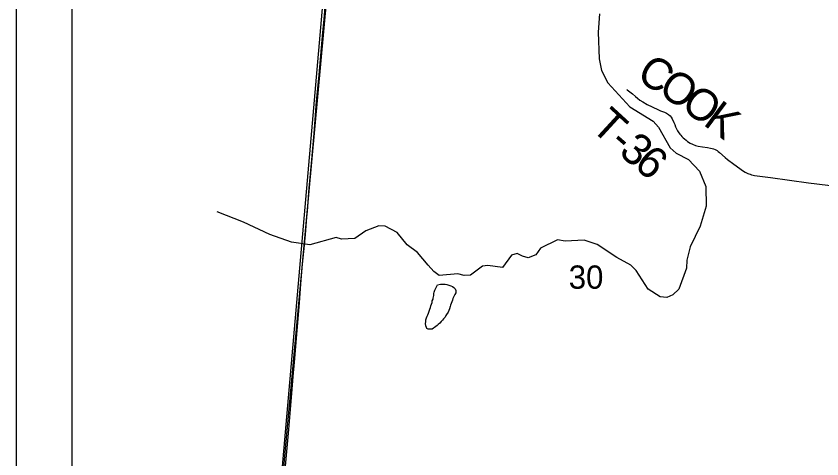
# Model space of a CAD drawing. Extents: x -19.5 to 44.1, y 0 to 22.
# Drawn here: x -19.313 to -17.865, y 16.054 to 16.851 of the extents above; entities that cross this region are included whole.
import ezdxf

# ---------------------------------------------------------------- set-up
doc = ezdxf.new("R2010")
doc.units = 0
for name, color, linetype in [('GM_X_County_Road', 7, 'Continuous'), ('GM_X_Minor_Lake', 7, 'Continuous'), ('GM_X_Minor_River', 7, 'Continuous'), ('GM_X_Section', 7, 'Continuous'), ('GM_X_Section_Text', 7, 'Continuous'), ('GM_X_Township', 7, 'Continuous'), ('GM_X_Township_Road', 7, 'Continuous'), ('GM_X_Township_Road_Text', 7, 'Continuous'), ('SH_Data', 7, 'Continuous')]:
    doc.layers.add(name, color=color, linetype=linetype)

msp = doc.modelspace()

# ---------------------------------------------------------------- linework, layer by layer
at = {"layer": 'GM_X_County_Road'}
msp.add_lwpolyline([(-18.8304, 16.0218), (-18.827, 16.0609), (-18.8229, 16.1073), (-18.8176, 16.1717), (-18.8151, 16.2027), (-18.8129, 16.228), (-18.8038, 16.3352), (-18.8012, 16.3686), (-18.7982, 16.4045), (-18.795, 16.4386), (-18.7932, 16.4577), (-18.792, 16.4732), (-18.7903, 16.4892), (-18.7893, 16.4998), (-18.7861, 16.5412), (-18.7824, 16.5858), (-18.7776, 16.6397), (-18.7729, 16.6973), (-18.7685, 16.7448), (-18.7615, 16.8213), (-18.7596, 16.8446), (-18.7578, 16.8675)], dxfattribs=at)
at = {"layer": 'GM_X_Minor_Lake'}
msp.add_lwpolyline([(-18.5556, 16.3673), (-18.5502, 16.3684), (-18.546, 16.3687), (-18.5419, 16.3686), (-18.5388, 16.3682), (-18.5354, 16.367), (-18.5316, 16.3655), (-18.529, 16.3643), (-18.5263, 16.3624), (-18.5241, 16.36), (-18.5226, 16.3574), (-18.523, 16.3532), (-18.5246, 16.3502), (-18.5258, 16.3475), (-18.5269, 16.3453), (-18.5281, 16.3426), (-18.5289, 16.34), (-18.5301, 16.3366), (-18.5312, 16.3335), (-18.5324, 16.3309), (-18.5332, 16.3286), (-18.5344, 16.3244), (-18.5364, 16.3184), (-18.5394, 16.3142), (-18.541, 16.312), (-18.5422, 16.3093), (-18.5449, 16.3063), (-18.5468, 16.3037), (-18.5491, 16.3011), (-18.5518, 16.2981), (-18.5545, 16.2962), (-18.5564, 16.2943), (-18.5587, 16.2921), (-18.5652, 16.2876), (-18.5694, 16.2876), (-18.5724, 16.2877), (-18.5747, 16.2885), (-18.5754, 16.2904), (-18.5769, 16.2938), (-18.5773, 16.2976), (-18.5768, 16.301), (-18.5764, 16.3041), (-18.5752, 16.3079), (-18.5741, 16.3109), (-18.5729, 16.3135), (-18.5721, 16.3166), (-18.5705, 16.32), (-18.5694, 16.3234), (-18.5682, 16.3268), (-18.5678, 16.3294), (-18.5666, 16.3325), (-18.5654, 16.3355), (-18.565, 16.3385), (-18.5635, 16.3415), (-18.5634, 16.3434), (-18.563, 16.3457), (-18.5622, 16.3484), (-18.5622, 16.3518), (-18.5614, 16.3541), (-18.5602, 16.3575), (-18.5556, 16.3673)], dxfattribs=at)
at = {"layer": 'GM_X_Minor_River'}
msp.add_lwpolyline([(-18.2646, 16.8548), (-18.2668, 16.8218), (-18.265, 16.7739), (-18.2609, 16.7529), (-18.2496, 16.731), (-18.2102, 16.6876), (-18.1682, 16.662), (-18.1585, 16.6508), (-18.1376, 16.6139), (-18.1268, 16.6041), (-18.1046, 16.5927), (-18.0846, 16.5717), (-18.0733, 16.5445), (-18.0729, 16.5088), (-18.0838, 16.4729), (-18.1016, 16.4357), (-18.1074, 16.4119), (-18.1081, 16.3974), (-18.1221, 16.3594), (-18.1325, 16.3493), (-18.1433, 16.3446), (-18.1558, 16.3456), (-18.1771, 16.3594), (-18.1985, 16.3929), (-18.2085, 16.4026), (-18.2333, 16.4165), (-18.2689, 16.4396), (-18.2919, 16.4477), (-18.3265, 16.4458), (-18.3401, 16.4484), (-18.3704, 16.4335), (-18.3789, 16.4215), (-18.3927, 16.4157), (-18.4029, 16.419), (-18.4127, 16.4234), (-18.4226, 16.4205), (-18.439, 16.3988), (-18.4651, 16.4024), (-18.475, 16.4008), (-18.4961, 16.3849), (-18.5076, 16.384), (-18.5193, 16.3873), (-18.5527, 16.3842), (-18.5624, 16.3912), (-18.5725, 16.4025), (-18.5917, 16.4253), (-18.6101, 16.4394), (-18.6279, 16.4614), (-18.65, 16.4729), (-18.6614, 16.4732), (-18.6847, 16.4642), (-18.704, 16.4505), (-18.7283, 16.4495), (-18.7381, 16.4524), (-18.785, 16.4394), (-18.8179, 16.4442), (-18.8568, 16.458), (-18.9041, 16.4803), (-18.9516, 16.4984)], dxfattribs=at)
at = {"layer": 'GM_X_Section'}
msp.add_line((-19.213, 16.9896), (-19.213, 15.9662), dxfattribs=at)
for points in [[(-19.213, 15.9662), (-18.8417, 15.9351), (-18.7487, 16.948), (-19.213, 16.9896)], [(-18.8417, 15.9351), (-18.7487, 16.948)]]:
    msp.add_lwpolyline(points, dxfattribs=at)
at = {"layer": 'GM_X_Township'}
msp.add_lwpolyline([(-17.3561, 18.1443), (-17.4643, 17.7858), (-17.649, 17.1741), (-17.7449, 16.8564), (-17.7682, 16.8751), (-17.7757, 16.8847), (-17.8063, 16.9097), (-17.826, 16.9172), (-17.8465, 16.92), (-17.8664, 16.9161), (-17.9065, 16.8978), (-17.926, 16.8931), (-18.0112, 16.8966), (-18.0543, 16.8933), (-18.1184, 16.8749), (-18.1478, 16.8725), (-18.1785, 16.8797), (-18.2096, 16.8937), (-18.2423, 16.9001), (-18.7562, 16.9411), (-18.7834, 16.6305), (-18.8446, 15.9307), (-18.9306, 14.9193), (-19.0014, 14.1)], dxfattribs=at)
at = {"layer": 'GM_X_Township_Road'}
msp.add_lwpolyline([(-18.2154, 16.7192), (-18.2149, 16.7183), (-18.2055, 16.7107), (-18.2001, 16.7062), (-18.1964, 16.703), (-18.1919, 16.6996), (-18.1867, 16.6964), (-18.1786, 16.692), (-18.17, 16.6875), (-18.1586, 16.6821), (-18.1547, 16.6804), (-18.1478, 16.678), (-18.144, 16.6762), (-18.1404, 16.6739), (-18.1377, 16.6715), (-18.1357, 16.6692), (-18.1339, 16.6661), (-18.131, 16.6594), (-18.1294, 16.6555), (-18.1277, 16.6516), (-18.1255, 16.6467), (-18.1244, 16.6446), (-18.1231, 16.6424), (-18.1203, 16.6385), (-18.1186, 16.6364), (-18.1167, 16.6344), (-18.1142, 16.632), (-18.1118, 16.6299), (-18.109, 16.6275), (-18.1061, 16.6254), (-18.1015, 16.6224), (-18.0972, 16.6201), (-18.0922, 16.6181), (-18.0873, 16.6169), (-18.0794, 16.6155), (-18.0703, 16.6143), (-18.0648, 16.6134), (-18.0621, 16.6128), (-18.0594, 16.612), (-18.0565, 16.6108), (-18.0533, 16.609), (-18.051, 16.6073), (-18.0489, 16.6056), (-18.0386, 16.5966), (-18.0343, 16.593), (-18.0229, 16.5844), (-18.0056, 16.5717), (-18.003, 16.5702), (-18.0005, 16.5689), (-17.9982, 16.5678), (-17.9961, 16.5669), (-17.9937, 16.5662), (-17.9911, 16.5654), (-17.9882, 16.5646), (-17.9858, 16.5641), (-17.9575, 16.5603), (-17.8889, 16.5509), (-17.8344, 16.544)], dxfattribs=at)
at = {"layer": 'SH_Data'}
for p, q in [((-19.313, 21), (-19.313, 14)), ((-19.213, 19.8563), (-19.213, 14.1))]:
    msp.add_line(p, q, dxfattribs=at)

# ---------------------------------------------------------------- texts
at = {"layer": 'GM_X_Section_Text'}
msp.add_text('30', height=0.04186, rotation=0, dxfattribs=at).set_placement((-18.3198, 16.3603))
at = {"layer": 'GM_X_Township_Road_Text'}
for s, rotation, p in [('C', 327.1641, (-18.2006, 16.7382)), ('O', 326.0755, (-18.1616, 16.7131)), ('O', 324.1706, (-18.1205, 16.6855)), ('K', 323.49, (-18.0801, 16.6563)), ('T', 317.4674, (-18.2822, 16.6487)), ('-', 319.0558, (-18.2496, 16.6188)), ('3', 319.1972, (-18.2319, 16.6035)), ('6', 319.7975, (-18.2049, 16.5802))]:
    msp.add_text(s, height=0.0568, rotation=rotation, dxfattribs=at).set_placement(p)

doc.saveas('drawing.dxf')
